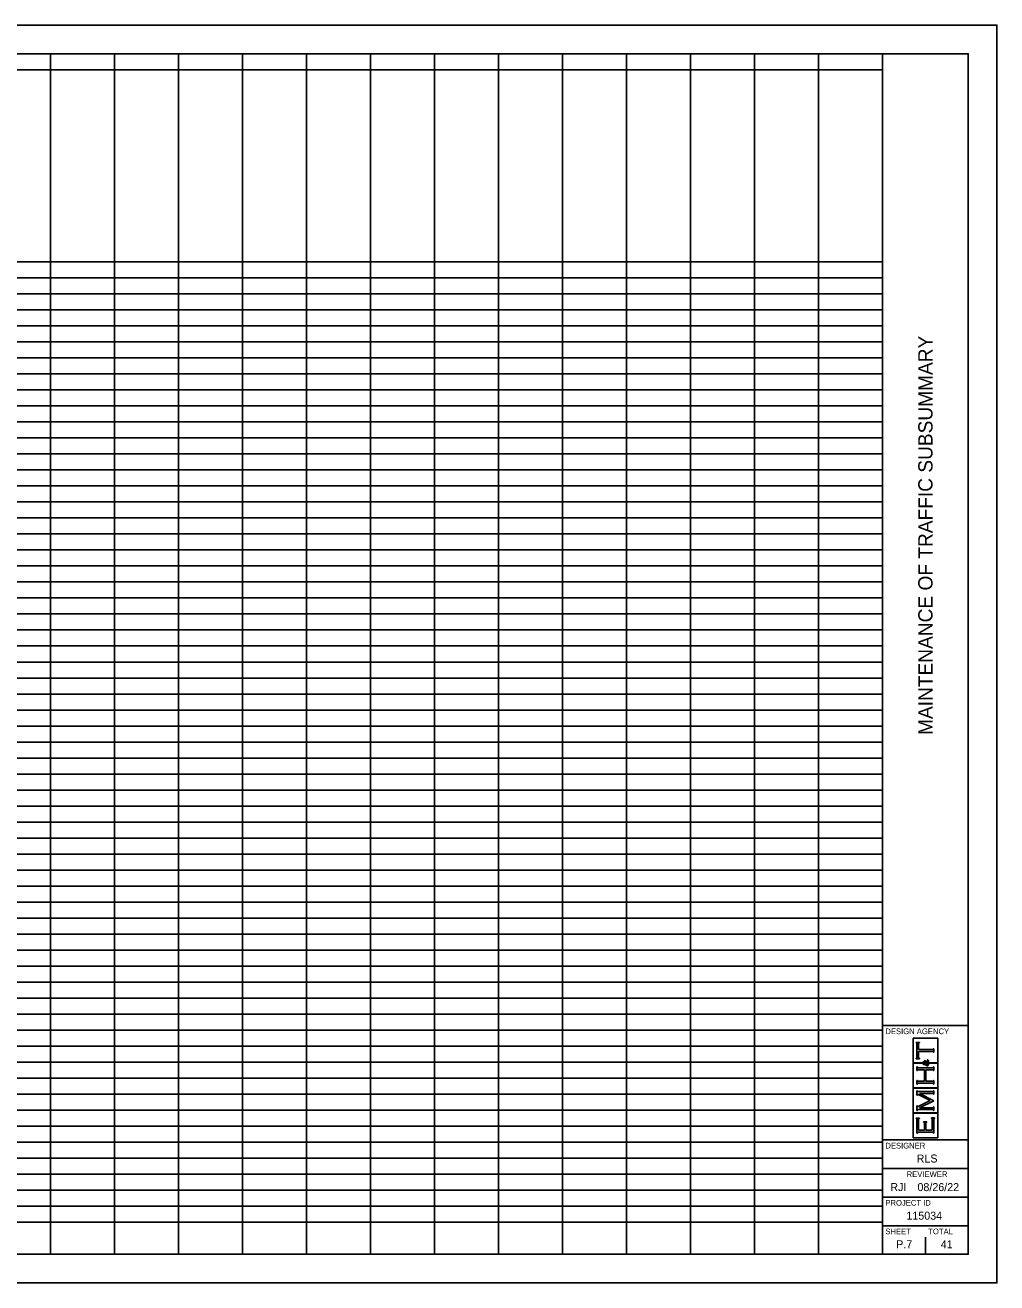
# Model space of a CAD drawing. Extents: x 0 to 34, y 0 to 22.
# Drawn here: x 17 to 34, y 0 to 22 of the extents above; entities that cross this region are included whole.
import ezdxf

# ---------------------------------------------------------------- set-up
doc = ezdxf.new("R2010")
doc.units = 0
for name, color, linetype in [('SH_Border', 7, 'Continuous'), ('SH_Cut_Line', 7, 'Continuous'), ('SH_Data', 7, 'Continuous'), ('SH_Text', 7, 'Continuous')]:
    doc.layers.add(name, color=color, linetype=linetype)

msp = doc.modelspace()

# ---------------------------------------------------------------- linework, layer by layer
at = {"layer": 'SH_Border'}
for p, q in [((32, 0.5), (32, 21.5)), ((32, 4.5), (33.5, 4.5)), ((32, 2.5), (33.5, 2.5)), ((32, 2), (33.5, 2)), ((32, 1.5), (33.5, 1.5)), ((32, 1), (33.5, 1))]:
    msp.add_line(p, q, dxfattribs=at)
msp.add_lwpolyline([(1.5, 21.5), (33.5, 21.5), (33.5, 0.5), (1.5, 0.5)], close=True, dxfattribs=at)
at = {"layer": 'SH_Cut_Line'}
msp.add_lwpolyline([(0, 0), (34, 0), (34, 22), (0, 22)], close=True, dxfattribs=at)
at = {"layer": 'SH_Data'}
for p, q in [((32.966, 4.28), (32.534, 4.28)), ((32.534, 4.28), (32.534, 3.848)), ((32.588, 4.199), (32.588, 4.206)), ((32.588, 4.206), (32.644, 4.206)), ((32.594, 4.198), (32.588, 4.199)), ((32.598, 4.196), (32.594, 4.198)), ((32.599, 4.194), (32.598, 4.196)), ((32.601, 4.191), (32.599, 4.194)), ((32.602, 4.187), (32.601, 4.191)), ((32.602, 4.181), (32.602, 4.187)), ((32.602, 3.947), (32.602, 4.181)), ((32.632, 4.191), (32.631, 4.187)), ((32.631, 4.187), (32.631, 4.181)), ((32.631, 4.181), (32.631, 4.081)), ((32.633, 4.194), (32.632, 4.191)), ((32.635, 4.196), (32.633, 4.194)), ((32.639, 4.198), (32.635, 4.196)), ((32.644, 4.199), (32.639, 4.198)), ((32.644, 4.206), (32.644, 4.199)), ((32.966, 3.848), (32.966, 4.28)), ((32.631, 4.081), (32.872, 4.081)), ((32.872, 4.047), (32.631, 4.047)), ((32.631, 4.047), (32.631, 3.947)), ((32.872, 4.081), (32.878, 4.081)), ((32.878, 4.047), (32.872, 4.047)), ((32.878, 4.081), (32.882, 4.082)), ((32.883, 4.046), (32.878, 4.047)), ((32.882, 4.082), (32.885, 4.084)), ((32.885, 4.044), (32.883, 4.046)), ((32.885, 4.084), (32.887, 4.085)), ((32.888, 4.042), (32.885, 4.044)), ((32.887, 4.085), (32.889, 4.089)), ((32.889, 4.039), (32.888, 4.042)), ((32.889, 4.089), (32.891, 4.095)), ((32.891, 4.033), (32.889, 4.039)), ((32.891, 4.095), (32.898, 4.095)), ((32.898, 4.033), (32.891, 4.033)), ((32.898, 4.095), (32.898, 4.033)), ((32.534, 3.848), (32.693, 3.848)), ((32.693, 3.842), (32.534, 3.842)), ((32.534, 3.842), (32.534, 3.41)), ((32.588, 3.928), (32.594, 3.93)), ((32.588, 3.921), (32.588, 3.928)), ((32.644, 3.921), (32.588, 3.921)), ((32.594, 3.93), (32.598, 3.932)), ((32.598, 3.932), (32.599, 3.934)), ((32.599, 3.934), (32.601, 3.937)), ((32.601, 3.937), (32.602, 3.941)), ((32.602, 3.941), (32.602, 3.947)), ((32.602, 3.714), (32.602, 3.776)), ((32.602, 3.776), (32.609, 3.776)), ((32.609, 3.776), (32.611, 3.77)), ((32.611, 3.77), (32.612, 3.766)), ((32.612, 3.766), (32.615, 3.765)), ((32.615, 3.765), (32.617, 3.763)), ((32.617, 3.763), (32.622, 3.762)), ((32.622, 3.762), (32.628, 3.762)), ((32.628, 3.762), (32.872, 3.762)), ((32.631, 3.947), (32.631, 3.941)), ((32.631, 3.941), (32.632, 3.937)), ((32.632, 3.937), (32.633, 3.934)), ((32.633, 3.934), (32.635, 3.932)), ((32.635, 3.932), (32.639, 3.93)), ((32.639, 3.93), (32.644, 3.928)), ((32.644, 3.928), (32.644, 3.921)), ((32.693, 3.848), (32.693, 3.842)), ((32.701, 3.852), (32.703, 3.857)), ((32.701, 3.846), (32.701, 3.852)), ((32.701, 3.84), (32.701, 3.846)), ((32.703, 3.835), (32.701, 3.84)), ((32.703, 3.857), (32.706, 3.861)), ((32.706, 3.83), (32.703, 3.835)), ((32.706, 3.861), (32.71, 3.864)), ((32.707, 3.852), (32.706, 3.849)), ((32.706, 3.849), (32.706, 3.846)), ((32.706, 3.846), (32.706, 3.842)), ((32.706, 3.842), (32.708, 3.839)), ((32.71, 3.824), (32.706, 3.83)), ((32.71, 3.854), (32.707, 3.852)), ((32.708, 3.839), (32.711, 3.837)), ((32.71, 3.864), (32.714, 3.866)), ((32.712, 3.856), (32.71, 3.854)), ((32.717, 3.821), (32.71, 3.824)), ((32.711, 3.837), (32.714, 3.835)), ((32.715, 3.857), (32.712, 3.856)), ((32.714, 3.866), (32.719, 3.866)), ((32.714, 3.835), (32.716, 3.834)), ((32.718, 3.857), (32.715, 3.857)), ((32.716, 3.834), (32.719, 3.834)), ((32.725, 3.821), (32.717, 3.821)), ((32.723, 3.857), (32.718, 3.857)), ((32.719, 3.866), (32.724, 3.866)), ((32.719, 3.834), (32.722, 3.834)), ((32.722, 3.834), (32.724, 3.834)), ((32.727, 3.856), (32.723, 3.857)), ((32.724, 3.866), (32.728, 3.864)), ((32.724, 3.834), (32.727, 3.835)), ((32.728, 3.821), (32.725, 3.821)), ((32.73, 3.853), (32.727, 3.856)), ((32.727, 3.835), (32.73, 3.836)), ((32.728, 3.864), (32.732, 3.861)), ((32.731, 3.822), (32.728, 3.821)), ((32.734, 3.85), (32.73, 3.853)), ((32.73, 3.836), (32.734, 3.837)), ((32.734, 3.822), (32.731, 3.822)), ((32.732, 3.861), (32.736, 3.857)), ((32.737, 3.845), (32.734, 3.85)), ((32.734, 3.837), (32.74, 3.839)), ((32.737, 3.823), (32.734, 3.822)), ((32.736, 3.857), (32.74, 3.851)), ((32.74, 3.839), (32.737, 3.845)), ((32.741, 3.825), (32.737, 3.823)), ((32.738, 3.867), (32.738, 3.898)), ((32.738, 3.898), (32.741, 3.898)), ((32.741, 3.867), (32.738, 3.867)), ((32.74, 3.851), (32.745, 3.842)), ((32.741, 3.898), (32.741, 3.894)), ((32.741, 3.894), (32.742, 3.891)), ((32.742, 3.871), (32.741, 3.869)), ((32.741, 3.869), (32.741, 3.867)), ((32.746, 3.827), (32.741, 3.825)), ((32.742, 3.891), (32.744, 3.889)), ((32.743, 3.872), (32.742, 3.871)), ((32.745, 3.873), (32.743, 3.872)), ((32.744, 3.889), (32.745, 3.887)), ((32.745, 3.887), (32.75, 3.883)), ((32.747, 3.874), (32.745, 3.873)), ((32.745, 3.842), (32.755, 3.848)), ((32.753, 3.815), (32.746, 3.827)), ((32.749, 3.874), (32.747, 3.874)), ((32.756, 3.874), (32.749, 3.874)), ((32.75, 3.883), (32.757, 3.879)), ((32.757, 3.832), (32.751, 3.829)), ((32.751, 3.829), (32.755, 3.824)), ((32.759, 3.808), (32.753, 3.815)), ((32.755, 3.848), (32.765, 3.855)), ((32.755, 3.824), (32.758, 3.819)), ((32.764, 3.87), (32.756, 3.874)), ((32.757, 3.879), (32.765, 3.875)), ((32.762, 3.835), (32.757, 3.832)), ((32.758, 3.819), (32.762, 3.817)), ((32.765, 3.803), (32.759, 3.808)), ((32.766, 3.838), (32.762, 3.835)), ((32.762, 3.817), (32.766, 3.814)), ((32.775, 3.861), (32.764, 3.87)), ((32.765, 3.875), (32.772, 3.87)), ((32.765, 3.855), (32.775, 3.861)), ((32.77, 3.799), (32.765, 3.803)), ((32.77, 3.84), (32.766, 3.838)), ((32.766, 3.814), (32.771, 3.812)), ((32.776, 3.845), (32.77, 3.84)), ((32.776, 3.797), (32.77, 3.799)), ((32.771, 3.812), (32.775, 3.812)), ((32.772, 3.87), (32.779, 3.865)), ((32.775, 3.812), (32.78, 3.812)), ((32.785, 3.851), (32.776, 3.845)), ((32.782, 3.797), (32.776, 3.797)), ((32.779, 3.865), (32.784, 3.869)), ((32.78, 3.812), (32.785, 3.814)), ((32.781, 3.9), (32.783, 3.902)), ((32.785, 3.899), (32.781, 3.9)), ((32.788, 3.797), (32.782, 3.797)), ((32.783, 3.902), (32.79, 3.901)), ((32.784, 3.869), (32.787, 3.873)), ((32.788, 3.897), (32.785, 3.899)), ((32.789, 3.846), (32.785, 3.851)), ((32.785, 3.814), (32.789, 3.817)), ((32.787, 3.873), (32.789, 3.876)), ((32.789, 3.895), (32.788, 3.897)), ((32.793, 3.8), (32.788, 3.797)), ((32.791, 3.892), (32.789, 3.895)), ((32.789, 3.876), (32.791, 3.88)), ((32.794, 3.859), (32.789, 3.855)), ((32.789, 3.855), (32.795, 3.849)), ((32.792, 3.842), (32.789, 3.846)), ((32.789, 3.817), (32.793, 3.821)), ((32.79, 3.901), (32.795, 3.898)), ((32.792, 3.89), (32.791, 3.892)), ((32.791, 3.88), (32.792, 3.883)), ((32.792, 3.886), (32.792, 3.89)), ((32.792, 3.883), (32.792, 3.886)), ((32.793, 3.839), (32.792, 3.842)), ((32.794, 3.837), (32.793, 3.839)), ((32.793, 3.821), (32.795, 3.825)), ((32.797, 3.804), (32.793, 3.8)), ((32.798, 3.864), (32.794, 3.859)), ((32.795, 3.834), (32.794, 3.837)), ((32.795, 3.898), (32.799, 3.894)), ((32.795, 3.849), (32.798, 3.843)), ((32.795, 3.831), (32.795, 3.834)), ((32.795, 3.825), (32.795, 3.831)), ((32.801, 3.809), (32.797, 3.804)), ((32.8, 3.868), (32.798, 3.864)), ((32.798, 3.843), (32.8, 3.839)), ((32.799, 3.894), (32.802, 3.89)), ((32.802, 3.872), (32.8, 3.868)), ((32.8, 3.839), (32.802, 3.834)), ((32.803, 3.815), (32.801, 3.809)), ((32.802, 3.89), (32.803, 3.885)), ((32.803, 3.876), (32.802, 3.872)), ((32.802, 3.834), (32.803, 3.829)), ((32.803, 3.885), (32.803, 3.88)), ((32.803, 3.88), (32.803, 3.876)), ((32.807, 3.842), (32.803, 3.848)), ((32.803, 3.848), (32.966, 3.848)), ((32.803, 3.829), (32.803, 3.823)), ((32.803, 3.823), (32.803, 3.815)), ((32.966, 3.842), (32.807, 3.842)), ((32.872, 3.762), (32.878, 3.762)), ((32.878, 3.762), (32.882, 3.763)), ((32.882, 3.763), (32.885, 3.765)), ((32.885, 3.765), (32.887, 3.766)), ((32.887, 3.766), (32.889, 3.77)), ((32.889, 3.77), (32.891, 3.776)), ((32.891, 3.776), (32.898, 3.776)), ((32.898, 3.776), (32.898, 3.714)), ((32.966, 3.41), (32.966, 3.842)), ((32.609, 3.714), (32.602, 3.714)), ((32.602, 3.477), (32.602, 3.538)), ((32.602, 3.538), (32.609, 3.538)), ((32.61, 3.72), (32.609, 3.714)), ((32.609, 3.538), (32.611, 3.533)), ((32.612, 3.723), (32.61, 3.72)), ((32.611, 3.533), (32.612, 3.529)), ((32.615, 3.725), (32.612, 3.723)), ((32.612, 3.529), (32.615, 3.527)), ((32.617, 3.727), (32.615, 3.725)), ((32.615, 3.527), (32.617, 3.526)), ((32.622, 3.728), (32.617, 3.727)), ((32.617, 3.526), (32.622, 3.525)), ((32.628, 3.728), (32.622, 3.728)), ((32.622, 3.525), (32.628, 3.525)), ((32.732, 3.728), (32.628, 3.728)), ((32.628, 3.525), (32.732, 3.525)), ((32.732, 3.525), (32.732, 3.728)), ((32.872, 3.728), (32.76, 3.728)), ((32.76, 3.728), (32.76, 3.525)), ((32.76, 3.525), (32.872, 3.525)), ((32.878, 3.728), (32.872, 3.728)), ((32.872, 3.525), (32.878, 3.525)), ((32.883, 3.727), (32.878, 3.728)), ((32.878, 3.525), (32.883, 3.525)), ((32.885, 3.725), (32.883, 3.727)), ((32.883, 3.525), (32.885, 3.527)), ((32.888, 3.723), (32.885, 3.725)), ((32.885, 3.527), (32.888, 3.529)), ((32.889, 3.72), (32.888, 3.723)), ((32.888, 3.529), (32.889, 3.533)), ((32.891, 3.714), (32.889, 3.72)), ((32.889, 3.533), (32.891, 3.538)), ((32.898, 3.714), (32.891, 3.714)), ((32.891, 3.538), (32.898, 3.538)), ((32.898, 3.538), (32.898, 3.477)), ((32.534, 3.41), (32.966, 3.41)), ((32.966, 3.405), (32.534, 3.405)), ((32.534, 3.405), (32.534, 2.973)), ((32.609, 3.477), (32.602, 3.477)), ((32.602, 3.283), (32.602, 3.36)), ((32.602, 3.36), (32.609, 3.36)), ((32.61, 3.482), (32.609, 3.477)), ((32.609, 3.36), (32.611, 3.354)), ((32.612, 3.486), (32.61, 3.482)), ((32.611, 3.354), (32.612, 3.351)), ((32.615, 3.488), (32.612, 3.486)), ((32.612, 3.351), (32.615, 3.349)), ((32.617, 3.49), (32.615, 3.488)), ((32.615, 3.349), (32.617, 3.347)), ((32.622, 3.491), (32.617, 3.49)), ((32.617, 3.347), (32.622, 3.346)), ((32.628, 3.491), (32.622, 3.491)), ((32.622, 3.346), (32.628, 3.346)), ((32.872, 3.491), (32.628, 3.491)), ((32.628, 3.346), (32.872, 3.346)), ((32.872, 3.312), (32.649, 3.312)), ((32.649, 3.312), (32.898, 3.186)), ((32.75, 3.5), (32.75, 3.5)), ((32.878, 3.491), (32.872, 3.491)), ((32.872, 3.346), (32.878, 3.346)), ((32.878, 3.312), (32.872, 3.312)), ((32.883, 3.49), (32.878, 3.491)), ((32.878, 3.346), (32.882, 3.347)), ((32.883, 3.311), (32.878, 3.312)), ((32.882, 3.347), (32.885, 3.349)), ((32.885, 3.488), (32.883, 3.49)), ((32.885, 3.31), (32.883, 3.311)), ((32.887, 3.486), (32.885, 3.488)), ((32.885, 3.349), (32.887, 3.351)), ((32.887, 3.308), (32.885, 3.31)), ((32.887, 3.351), (32.889, 3.354)), ((32.889, 3.304), (32.887, 3.308)), ((32.889, 3.482), (32.887, 3.486)), ((32.891, 3.477), (32.889, 3.482)), ((32.889, 3.354), (32.891, 3.36)), ((32.891, 3.298), (32.889, 3.304)), ((32.898, 3.477), (32.891, 3.477)), ((32.891, 3.36), (32.898, 3.36)), ((32.898, 3.36), (32.898, 3.298)), ((32.966, 2.973), (32.966, 3.405)), ((32.609, 3.283), (32.602, 3.283)), ((32.602, 3.017), (32.602, 3.094)), ((32.602, 3.094), (32.609, 3.094)), ((32.612, 3.29), (32.609, 3.283)), ((32.609, 3.094), (32.612, 3.087)), ((32.615, 3.293), (32.612, 3.29)), ((32.612, 3.087), (32.615, 3.083)), ((32.618, 3.293), (32.615, 3.293)), ((32.615, 3.083), (32.618, 3.083)), ((32.621, 3.293), (32.618, 3.293)), ((32.618, 3.083), (32.62, 3.083)), ((32.62, 3.083), (32.625, 3.086)), ((32.626, 3.292), (32.621, 3.293)), ((32.625, 3.086), (32.635, 3.09)), ((32.633, 3.288), (32.626, 3.292)), ((32.831, 3.189), (32.633, 3.288)), ((32.635, 3.09), (32.831, 3.189)), ((32.898, 3.186), (32.649, 3.062)), ((32.898, 3.298), (32.891, 3.298)), ((32.534, 2.973), (32.966, 2.973)), ((32.966, 2.967), (32.534, 2.967)), ((32.534, 2.967), (32.534, 2.535)), ((32.588, 2.874), (32.588, 2.881)), ((32.588, 2.881), (32.644, 2.881)), ((32.594, 2.873), (32.588, 2.874)), ((32.598, 2.871), (32.594, 2.873)), ((32.599, 2.868), (32.598, 2.871)), ((32.601, 2.866), (32.599, 2.868)), ((32.602, 2.862), (32.601, 2.866)), ((32.609, 3.017), (32.602, 3.017)), ((32.602, 2.856), (32.602, 2.862)), ((32.61, 3.023), (32.609, 3.017)), ((32.612, 3.026), (32.61, 3.023)), ((32.615, 3.028), (32.612, 3.026)), ((32.617, 3.03), (32.615, 3.028)), ((32.622, 3.031), (32.617, 3.03)), ((32.628, 3.031), (32.622, 3.031)), ((32.872, 3.031), (32.628, 3.031)), ((32.632, 2.866), (32.631, 2.862)), ((32.631, 2.862), (32.631, 2.856)), ((32.633, 2.868), (32.632, 2.866)), ((32.635, 2.871), (32.633, 2.868)), ((32.639, 2.873), (32.635, 2.871)), ((32.644, 2.874), (32.639, 2.873)), ((32.644, 2.881), (32.644, 2.874)), ((32.649, 3.062), (32.872, 3.062)), ((32.855, 2.877), (32.855, 2.884)), ((32.855, 2.884), (32.912, 2.884)), ((32.861, 2.876), (32.855, 2.877)), ((32.865, 2.874), (32.861, 2.876)), ((32.867, 2.872), (32.865, 2.874)), ((32.868, 2.869), (32.867, 2.872)), ((32.869, 2.865), (32.868, 2.869)), ((32.869, 2.859), (32.869, 2.865)), ((32.872, 3.062), (32.878, 3.062)), ((32.878, 3.031), (32.872, 3.031)), ((32.878, 3.062), (32.882, 3.063)), ((32.883, 3.03), (32.878, 3.031)), ((32.882, 3.063), (32.885, 3.065)), ((32.885, 3.028), (32.883, 3.03)), ((32.885, 3.065), (32.887, 3.067)), ((32.887, 3.026), (32.885, 3.028)), ((32.887, 3.067), (32.889, 3.07)), ((32.889, 3.023), (32.887, 3.026)), ((32.889, 3.07), (32.891, 3.076)), ((32.891, 3.017), (32.889, 3.023)), ((32.891, 3.076), (32.898, 3.076)), ((32.898, 3.017), (32.891, 3.017)), ((32.898, 3.076), (32.898, 3.017)), ((32.899, 2.869), (32.898, 2.865)), ((32.898, 2.865), (32.898, 2.858)), ((32.901, 2.871), (32.899, 2.869)), ((32.903, 2.874), (32.901, 2.871)), ((32.906, 2.876), (32.903, 2.874)), ((32.912, 2.877), (32.906, 2.876)), ((32.912, 2.884), (32.912, 2.877)), ((32.966, 2.535), (32.966, 2.967)), ((32.602, 2.621), (32.602, 2.856)), ((32.631, 2.856), (32.631, 2.669)), ((32.631, 2.669), (32.732, 2.669)), ((32.718, 2.81), (32.718, 2.816)), ((32.718, 2.816), (32.774, 2.816)), ((32.723, 2.808), (32.718, 2.81)), ((32.727, 2.806), (32.723, 2.808)), ((32.729, 2.804), (32.727, 2.806)), ((32.731, 2.801), (32.729, 2.804)), ((32.732, 2.797), (32.731, 2.801)), ((32.732, 2.791), (32.732, 2.797)), ((32.732, 2.669), (32.732, 2.791)), ((32.761, 2.801), (32.76, 2.797)), ((32.76, 2.797), (32.76, 2.791)), ((32.76, 2.791), (32.76, 2.669)), ((32.76, 2.669), (32.869, 2.669)), ((32.763, 2.804), (32.761, 2.801)), ((32.765, 2.806), (32.763, 2.804)), ((32.768, 2.808), (32.765, 2.806)), ((32.774, 2.81), (32.768, 2.808)), ((32.774, 2.816), (32.774, 2.81)), ((32.869, 2.669), (32.869, 2.859)), ((32.898, 2.858), (32.898, 2.621)), ((32.534, 2.535), (32.966, 2.535)), ((32.609, 2.621), (32.602, 2.621)), ((32.611, 2.626), (32.609, 2.621)), ((32.612, 2.63), (32.611, 2.626)), ((32.615, 2.632), (32.612, 2.63)), ((32.617, 2.634), (32.615, 2.632)), ((32.622, 2.635), (32.617, 2.634)), ((32.628, 2.635), (32.622, 2.635)), ((32.872, 2.635), (32.628, 2.635)), ((32.878, 2.635), (32.872, 2.635)), ((32.883, 2.634), (32.878, 2.635)), ((32.885, 2.632), (32.883, 2.634)), ((32.887, 2.63), (32.885, 2.632)), ((32.889, 2.627), (32.887, 2.63)), ((32.891, 2.621), (32.889, 2.627)), ((32.898, 2.621), (32.891, 2.621)), ((32.375, 0.675), (32.375, 0.675)), ((32.75, 0.5), (32.75, 0.8))]:
    msp.add_line(p, q, dxfattribs=at)
at = {"layer": 'SH_Text'}
for p, q in [((1.5, 21.5), (32, 21.5)), ((17.442, 21.5), (17.442, 0.5)), ((18.562, 21.5), (18.562, 0.5)), ((19.681, 21.5), (19.681, 0.5)), ((20.801, 21.5), (20.801, 0.5)), ((21.921, 21.5), (21.921, 0.5)), ((23.041, 21.5), (23.041, 0.5)), ((24.161, 21.5), (24.161, 0.5)), ((25.281, 21.5), (25.281, 0.5)), ((26.401, 21.5), (26.401, 0.5)), ((27.521, 21.5), (27.521, 0.5)), ((28.64, 21.5), (28.64, 0.5)), ((29.76, 21.5), (29.76, 0.5)), ((30.88, 21.5), (30.88, 0.5)), ((32, 21.5), (32, 0.5)), ((5.123, 21.22), (32, 21.22)), ((5.123, 17.86), (32, 17.86)), ((1.5, 17.58), (32, 17.58)), ((1.5, 17.3), (32, 17.3)), ((1.5, 17.02), (32, 17.02)), ((1.5, 16.74), (32, 16.74)), ((1.5, 16.46), (32, 16.46)), ((1.5, 16.18), (32, 16.18)), ((1.5, 15.9), (32, 15.9)), ((1.5, 15.62), (32, 15.62)), ((1.5, 15.34), (32, 15.34)), ((1.5, 15.06), (32, 15.06)), ((1.5, 14.78), (32, 14.78)), ((1.5, 14.5), (32, 14.5)), ((1.5, 14.22), (32, 14.22)), ((1.5, 13.94), (32, 13.94)), ((1.5, 13.66), (32, 13.66)), ((1.5, 13.38), (32, 13.38)), ((1.5, 13.1), (32, 13.1)), ((1.5, 12.82), (32, 12.82)), ((1.5, 12.54), (32, 12.54)), ((1.5, 12.26), (32, 12.26)), ((1.5, 11.98), (32, 11.98)), ((1.5, 11.7), (32, 11.7)), ((1.5, 11.42), (32, 11.42)), ((1.5, 11.14), (32, 11.14)), ((1.5, 10.86), (32, 10.86)), ((1.5, 10.58), (32, 10.58)), ((1.5, 10.3), (32, 10.3)), ((1.5, 10.02), (32, 10.02)), ((1.5, 9.74), (32, 9.74)), ((1.5, 9.46), (32, 9.46)), ((1.5, 9.18), (32, 9.18)), ((1.5, 8.9), (32, 8.9)), ((1.5, 8.62), (32, 8.62)), ((1.5, 8.34), (32, 8.34)), ((1.5, 8.06), (32, 8.06)), ((1.5, 7.78), (32, 7.78)), ((1.5, 7.5), (32, 7.5)), ((1.5, 7.22), (32, 7.22)), ((1.5, 6.94), (32, 6.94)), ((1.5, 6.66), (32, 6.66)), ((1.5, 6.38), (32, 6.38)), ((1.5, 6.1), (32, 6.1)), ((1.5, 5.82), (32, 5.82)), ((1.5, 5.54), (32, 5.54)), ((1.5, 5.26), (32, 5.26)), ((1.5, 4.98), (32, 4.98)), ((1.5, 4.7), (32, 4.7)), ((1.5, 4.42), (32, 4.42)), ((1.5, 4.14), (32, 4.14)), ((1.5, 3.86), (32, 3.86)), ((1.5, 3.58), (32, 3.58)), ((1.5, 3.3), (32, 3.3)), ((1.5, 3.02), (32, 3.02)), ((1.5, 2.74), (32, 2.74)), ((1.5, 2.46), (32, 2.46)), ((1.5, 2.18), (32, 2.18)), ((1.5, 1.9), (32, 1.9)), ((1.5, 1.62), (32, 1.62)), ((1.5, 1.34), (32, 1.34)), ((1.5, 1.06), (32, 1.06)), ((1.5, 0.5), (32, 0.5))]:
    msp.add_line(p, q, dxfattribs=at)

# ---------------------------------------------------------------- texts
at = {"layer": 'SH_Data'}
msp.add_text('MAINTENANCE OF TRAFFIC SUBSUMMARY', height=0.25, rotation=90, dxfattribs=at).set_placement((32.875, 9.584))
for s, height, p in [('DESIGN AGENCY', 0.1, (32.05, 4.35)), ('DESIGNER', 0.1, (32.05, 2.35)), ('RLS', 0.14, (32.597, 2.105)), ('REVIEWER', 0.1, (32.422, 1.85)), ('RJI', 0.14, (32.136, 1.605)), ('08/26/22', 0.14, (32.611, 1.605)), ('PROJECT ID', 0.1, (32.05, 1.35)), ('115034', 0.14, (32.418, 1.105)), ('SHEET', 0.1, (32.05, 0.85)), ('TOTAL', 0.1, (32.8, 0.85)), ('P.7', 0.14, (32.239, 0.605)), ('41', 0.14, (33.019, 0.605))]:
    msp.add_text(s, height=height, dxfattribs=at).set_placement(p)

doc.saveas('drawing.dxf')
